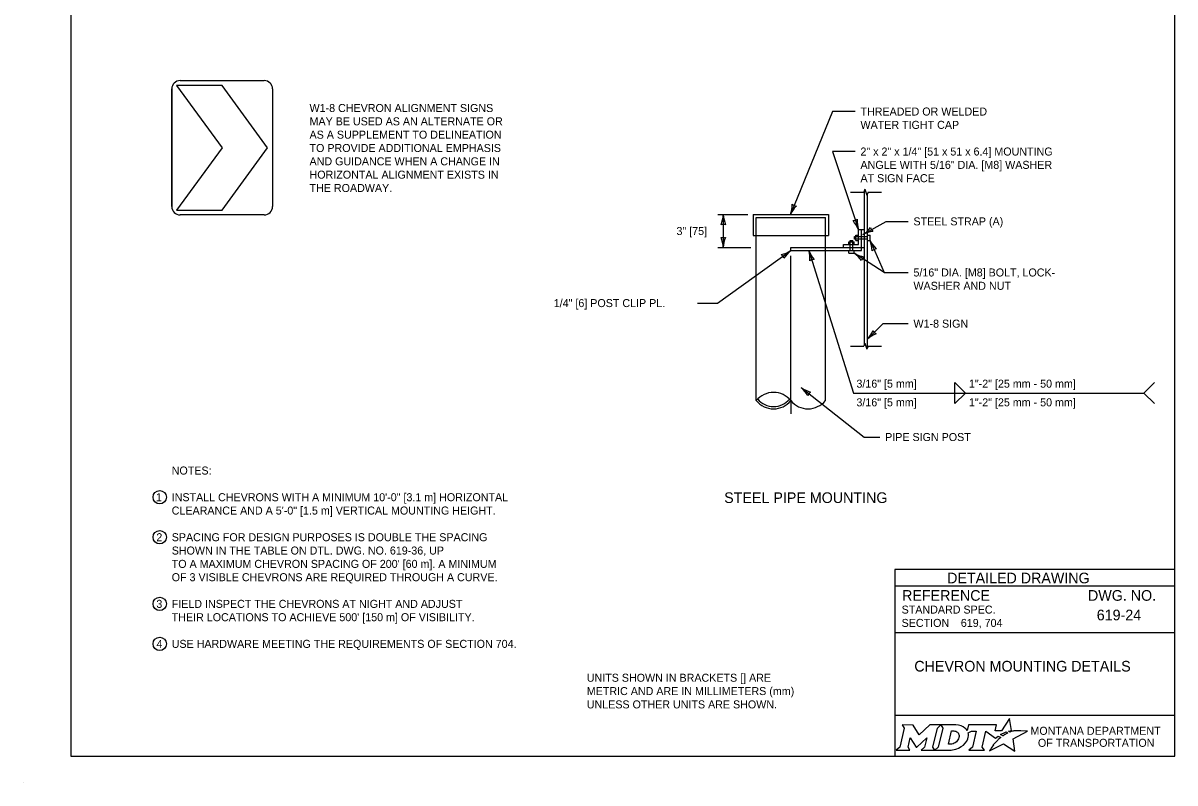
# Model space of a CAD drawing. Extents: x 49991.4 to 50021, y 49987.6 to 50011.4.
# Drawn here: x 49999.98 to 50008.61, y 49999.86 to 50005.56 of the extents above; entities that cross this region are included whole.
import ezdxf

# ---------------------------------------------------------------- set-up
doc = ezdxf.new("R2010")
doc.units = 0
for name, color, linetype in [('Level 1', 7, 'Continuous'), ('Level 2', 7, 'Continuous'), ('Level 3', 7, 'Continuous'), ('Level 4', 7, 'Continuous'), ('Level 5', 7, 'Continuous'), ('Level 6', 7, 'Continuous')]:
    doc.layers.add(name, color=color, linetype=linetype)

msp = doc.modelspace()

# ---------------------------------------------------------------- linework, layer by layer
at = {"layer": 'Level 1'}
for p, q in [((50001.1545, 50005.131), (50001.7845, 50005.131)), ((50001.0915, 50004.186), (50001.0915, 50005.068)), ((50001.0915, 50004.186), (50001.0915, 50005.068)), ((50001.0915, 50005.068), (50001.0915, 50004.186)), ((50001.4695, 50005.0943), (50001.1282, 50005.0943)), ((50001.1282, 50005.0943), (50001.4695, 50004.627)), ((50001.8107, 50004.627), (50001.4695, 50005.0943)), ((50001.8475, 50005.068), (50001.8475, 50004.186)), ((50001.4695, 50004.627), (50001.1282, 50004.1598)), ((50001.4695, 50004.1598), (50001.8107, 50004.627)), ((50006.2854, 50003.1528), (50006.2854, 50004.3074)), ((50006.3079, 50003.1248), (50006.3079, 50004.2794)), ((50001.1282, 50004.1598), (50001.4695, 50004.1598)), ((50001.7845, 50004.123), (50001.1545, 50004.123)), ((50005.4528, 50004.1261), (50006.0154, 50004.1261)), ((50005.4528, 50004.1261), (50005.4528, 50003.9686)), ((50006.0154, 50004.1261), (50006.0154, 50003.9686)), ((50006.2404, 50003.9011), (50006.2404, 50004.0136)), ((50006.2404, 50004.0136), (50006.2854, 50004.0136)), ((50006.2629, 50003.8561), (50006.2629, 50004.0136)), ((50005.4528, 50003.9686), (50006.0154, 50003.9686)), ((50005.4753, 50002.7302), (50005.4753, 50003.9686)), ((50005.9929, 50002.7308), (50005.9929, 50003.9686)), ((50006.1695, 50003.9211), (50006.2095, 50003.9211)), ((50006.1695, 50003.9011), (50006.1695, 50003.9211)), ((50006.1795, 50003.8561), (50006.1795, 50003.9311)), ((50006.1795, 50003.9311), (50006.1995, 50003.9311)), ((50006.1995, 50003.8561), (50006.1995, 50003.9311)), ((50006.2095, 50003.9011), (50006.2095, 50003.9211)), ((50006.2104, 50003.9411), (50006.2104, 50003.9611)), ((50006.2104, 50003.9611), (50006.3079, 50003.9611)), ((50006.3079, 50003.9411), (50006.2104, 50003.9411)), ((50006.2204, 50003.9311), (50006.2204, 50003.9711)), ((50006.2204, 50003.9711), (50006.2404, 50003.9711)), ((50006.2204, 50003.9311), (50006.2404, 50003.9311)), ((50006.3079, 50003.9711), (50006.3279, 50003.9711)), ((50006.3079, 50003.9311), (50006.3279, 50003.9311)), ((50006.3279, 50003.9311), (50006.3279, 50003.9711)), ((50005.7341, 50003.8786), (50006.2854, 50003.8786)), ((50005.7341, 50003.8561), (50005.7341, 50003.8786)), ((50005.7341, 50003.8561), (50006.2629, 50003.8561)), ((50006.1279, 50003.9011), (50006.2404, 50003.9011)), ((50006.1279, 50003.8786), (50006.1279, 50003.9011)), ((50006.1695, 50003.8361), (50006.1695, 50003.8561)), ((50006.1695, 50003.8361), (50006.2095, 50003.8361)), ((50006.2095, 50003.8361), (50006.2095, 50003.8561)), ((50006.2629, 50003.8561), (50006.2629, 50003.8786)), ((49999.9766, 49999.8624), (49999.9766, 49999.8624))]:
    msp.add_line(p, q, dxfattribs=at)
msp.add_lwpolyline([(50008.6146, 50011.2628), (50000.3356, 50011.2628), (50000.3356, 50000.0624), (50008.6146, 50000.0624)], close=True, dxfattribs=at)
for centre, radius, start, end in [((50001.1545, 50005.068), 0.063, 90, 180), ((50001.7845, 50005.068), 0.063, 0, 90), ((50001.1545, 50004.186), 0.063, 180, 270), ((50001.7845, 50004.186), 0.063, 270, 0), ((50005.6047, 50002.6249), 0.1668, 39.18708, 140.8762), ((50005.6047, 50002.8356), 0.1669, 219.16718, 320.85631), ((50005.6047, 50002.8388), 0.1534, 219.15498, 320.84411), ((50005.8633, 50002.8356), 0.1667, 219.17071, 321.03614)]:
    msp.add_arc(centre, radius, start, end, dxfattribs=at)
at = {"layer": 'Level 2'}
for p, q in [((50008.6146, 50001.4624), (50006.5146, 50001.4624)), ((50006.5146, 50001.4624), (50006.5146, 50000.0624)), ((50008.6146, 50001.3374), (50006.5146, 50001.3374)), ((50008.2507, 50001.1223), (50008.2507, 50001.1223)), ((50008.6146, 50000.9874), (50006.5146, 50000.9874)), ((50007.0089, 50001.0629), (50007.0089, 50001.0629)), ((50007.5646, 50000.7383), (50007.5646, 50000.7383)), ((50008.6146, 50000.3693), (50006.5146, 50000.3693))]:
    msp.add_line(p, q, dxfattribs=at)
for points in [[(50006.5701, 50000.2974), (50006.5842, 50000.274), (50006.5507, 50000.1307), (50006.525, 50000.1082), (50006.6266, 50000.1082), (50006.6131, 50000.131), (50006.6293, 50000.2011), (50006.673, 50000.1321), (50006.6783, 50000.1321), (50006.7534, 50000.2016), (50006.737, 50000.1305), (50006.7123, 50000.1085), (50006.8139, 50000.1085), (50006.8001, 50000.1318), (50006.8333, 50000.2742)], [(50006.8333, 50000.2742), (50006.8586, 50000.2974), (50006.7762, 50000.2974), (50006.6966, 50000.2244), (50006.6521, 50000.2971), (50006.5701, 50000.2974)], [(50006.9722, 50000.2974), (50006.8586, 50000.2974), (50006.8733, 50000.2745), (50006.8394, 50000.1307), (50006.8139, 50000.1085), (50006.9245, 50000.1085)], [(50007.3771, 50000.2447), (50007.3668, 50000.2503), (50007.3784, 50000.2531), (50007.39, 50000.2551), (50007.3726, 50000.3452), (50007.3131, 50000.2539), (50007.2658, 50000.2532), (50007.2761, 50000.2973), (50007.0669, 50000.2974), (50007.0568, 50000.2549), (50007.051, 50000.2632)], [(50006.9962, 50000.2107), (50006.995, 50000.2026), (50006.9918, 50000.1933), (50006.9876, 50000.1851), (50006.982, 50000.1776), (50006.9755, 50000.1707), (50006.9676, 50000.1644), (50006.9593, 50000.1597), (50006.9502, 50000.1558), (50006.9411, 50000.1535), (50006.9319, 50000.1526), (50006.916, 50000.1526), (50006.9396, 50000.2526), (50006.9556, 50000.2526), (50006.9632, 50000.252), (50006.9708, 50000.2501), (50006.9774, 50000.2471), (50006.9835, 50000.2429), (50006.9883, 50000.2379), (50006.992, 50000.2319), (50006.9947, 50000.2257), (50006.9963, 50000.2183), (50006.9963, 50000.2153), (50006.9962, 50000.2107)], [(50007.0636, 50000.2383), (50007.0882, 50000.2514), (50007.1251, 50000.2514), (50007.0965, 50000.1309), (50007.069, 50000.1082), (50007.1852, 50000.1082), (50007.1682, 50000.1311), (50007.1964, 50000.2513), (50007.2677, 50000.1996), (50007.2888, 50000.2147), (50007.3085, 50000.2038)], [(50007.2527, 50000.1479), (50007.2374, 50000.1235), (50007.2327, 50000.116), (50007.2269, 50000.1074), (50007.2246, 50000.1031), (50007.3299, 50000.1562), (50007.4138, 50000.1011), (50007.4007, 50000.1938), (50007.5076, 50000.2522), (50007.4583, 50000.253), (50007.4282, 50000.2534), (50007.4074, 50000.2537), (50007.4006, 50000.2522), (50007.3957, 50000.251), (50007.3873, 50000.2487), (50007.3771, 50000.2447)], [(50007.3267, 50000.2171), (50007.3243, 50000.2154), (50007.306, 50000.225), (50007.3163, 50000.2307), (50007.3204, 50000.2329), (50007.329, 50000.2369), (50007.3347, 50000.2395), (50007.3426, 50000.2425), (50007.3499, 50000.2452), (50007.3617, 50000.2378), (50007.3577, 50000.2357), (50007.3531, 50000.2332), (50007.3489, 50000.231), (50007.3439, 50000.2281), (50007.342, 50000.227), (50007.3393, 50000.2254), (50007.3368, 50000.224), (50007.3345, 50000.2224), (50007.3319, 50000.2206), (50007.3292, 50000.2188), (50007.3267, 50000.2171)], [(50006.9702, 50000.1158), (50006.9786, 50000.1184), (50006.9916, 50000.1238), (50007.012, 50000.1348)], [(50007.2666, 50000.164), (50007.2666, 50000.164)]]:
    msp.add_lwpolyline(points, dxfattribs=at)
for centre in [(50001.0015, 50002.0058), (50001.0015, 50001.7058), (50001.0015, 50001.2058), (50001.0015, 50000.9058)]:
    msp.add_circle(centre, 0.05, dxfattribs=at)
for centre, radius, start, end in [((50006.9953, 50000.219), 0.0709, 339.53292, 15.85821), ((50006.9513, 50000.2363), 0.1183, 300.91025, 339.13831)]:
    msp.add_arc(centre, radius, start, end, dxfattribs=at)
for centre, major_axis, ratio, start_param, end_param in [((50006.9701, 50000.25), (0.0834, -0.0037), 0.568097, 0.61298, 1.570796), ((50007.0257, 50000.2573), (0.0361, -0.0295), 0.469099, 1.225588, 1.570796), ((50007.2974, 50000.1941), (-0.0112, -0.0097), 0.021651, 3.157348, 6.283185), ((50006.9248, 50000.2568), (0, 0.1484), 0.987302, 3.139398, 3.456847), ((50007.2597, 50000.1559), (-0.00694, -0.00806), 0.008222, 0, 3.137361), ((50007.2764, 50000.1742), (-0.0098, -0.0102), 0.016458, 3.141593, 6.279097)]:
    msp.add_ellipse(centre, major_axis=major_axis, ratio=ratio, start_param=start_param, end_param=end_param, dxfattribs=at)
at = {"layer": 'Level 3'}
for p, q in [((50006.0462, 50004.8988), (50005.7313, 50004.1261)), ((50006.2162, 50004.8988), (50006.0462, 50004.8988)), ((50006.0462, 50004.5988), (50006.2404, 50004.0136)), ((50006.2162, 50004.5988), (50006.0462, 50004.5988)), ((50005.1878, 50004.1261), (50005.4128, 50004.1261)), ((50005.2278, 50004.1261), (50005.2278, 50003.8786)), ((50006.2746, 50003.9764), (50006.448, 50004.0747)), ((50006.448, 50004.0747), (50006.6137, 50004.0747)), ((50006.3279, 50003.9311), (50006.4349, 50003.6915)), ((50005.1845, 50003.4619), (50005.7341, 50003.8561)), ((50005.1878, 50003.8786), (50005.4353, 50003.8786)), ((50005.8701, 50003.8561), (50006.2045, 50002.7875)), ((50006.4349, 50003.6915), (50006.2095, 50003.8361)), ((50006.4349, 50003.6915), (50006.6137, 50003.6915)), ((50005.0332, 50003.4619), (50005.1845, 50003.4619)), ((50006.4272, 50003.3076), (50006.3079, 50003.1912)), ((50006.4272, 50003.3076), (50006.6137, 50003.3076)), ((50005.8125, 50002.8278), (50006.283, 50002.4571)), ((50006.9649, 50002.7075), (50006.9649, 50002.8675)), ((50006.2045, 50002.7875), (50008.38, 50002.7875)), ((50006.283, 50002.4571), (50006.4015, 50002.4571))]:
    msp.add_line(p, q, dxfattribs=at)
for points in [[(50006.9649, 50002.8675), (50007.0449, 50002.7875), (50006.9649, 50002.7075)], [(50008.46, 50002.7075), (50008.38, 50002.7875), (50008.46, 50002.8675)]]:
    msp.add_lwpolyline(points, dxfattribs=at)
for centre, radius, start, end in [((50005.5114, 50004.2033), 0.233, 340.65412, 359.90397), ((50005.9335, 50004.0338), 0.2223, 135.28282, 155.46633), ((50005.7797, 50004.2448), 0.0548, 229.96563, 265.68799), ((50005.0057, 50004.1353), 0.2223, 337.45601, 357.63952), ((50005.4605, 50004.1376), 0.233, 182.82731, 202.07716), ((50006.2, 50004.1353), 0.0548, 270.49737, 306.21973), ((50006.4541, 50004.0749), 0.2223, 175.81456, 195.99807), ((50005.2278, 50003.9979), 0.0548, 72.13882, 107.86118), ((50006.0232, 50003.9294), 0.233, 21.18586, 40.43571), ((50006.1498, 50004.1732), 0.233, 302.3761, 321.62595), ((50006.3861, 50004.0396), 0.0548, 191.68761, 227.40997), ((50005.2278, 50004.0068), 0.0548, 252.13882, 287.86118), ((50004.9951, 50003.8671), 0.233, 2.82731, 22.07716), ((50005.4499, 50003.8694), 0.2223, 157.45601, 177.63952), ((50006.3762, 50003.7786), 0.2223, 97.0048, 117.18831), ((50006.1213, 50003.8489), 0.2223, 1.52048, 21.70399), ((50006.5357, 50004.0365), 0.233, 206.89178, 226.14163), ((50005.6121, 50004.0419), 0.2223, 283.10595, 303.28946), ((50005.8791, 50003.6737), 0.233, 128.47725, 147.7271), ((50005.6554, 50003.7985), 0.2223, 354.83117, 15.01468), ((50006.0888, 50003.9366), 0.233, 200.20247, 219.45232), ((50006.0818, 50003.6541), 0.2223, 34.77142, 54.95493), ((50006.3255, 50004.0382), 0.233, 240.14272, 259.39257), ((50006.3802, 50003.814), 0.0548, 96.20329, 131.92565), ((50005.6299, 50003.7814), 0.0548, 17.78876, 53.51112), ((50005.9084, 50003.7337), 0.0548, 89.51398, 125.23634), ((50006.3174, 50003.7669), 0.0548, 129.45423, 165.17659), ((50006.1372, 50003.3497), 0.233, 317.12239, 336.37224), ((50006.4565, 50003.0258), 0.2223, 111.75109, 131.9346), ((50006.3997, 50003.2807), 0.0548, 206.4339, 242.15626), ((50005.6678, 50002.659), 0.2223, 29.22196, 49.40547), ((50005.9475, 50003.0177), 0.233, 234.59326, 253.84311), ((50005.9132, 50002.7485), 0.0548, 123.90477, 159.62713)]:
    msp.add_arc(centre, radius, start, end, dxfattribs=at)
at = {"layer": 'Level 4'}
for p, q in [((50005.4753, 50003.9686), (50005.4753, 50004.1036)), ((50005.4753, 50004.1036), (50005.9929, 50004.1036)), ((50005.9929, 50003.9686), (50005.9929, 50004.1036))]:
    msp.add_line(p, q, dxfattribs=at)
at = {"layer": 'Level 5'}
for q in [(50005.7341, 50003.8161), (50005.7341, 50002.6303)]:
    msp.add_line((50005.7341, 50002.7303), q, dxfattribs=at)
at = {"layer": 'Level 6'}
for p, q in [((50006.1805, 50004.2935), (50006.2805, 50004.2935)), ((50006.2886, 50004.3164), (50006.2805, 50004.2935)), ((50006.2886, 50004.3164), (50006.2967, 50004.2935)), ((50006.2967, 50004.2935), (50006.3048, 50004.2706)), ((50006.3129, 50004.2935), (50006.3048, 50004.2706)), ((50006.3129, 50004.2935), (50006.4129, 50004.2935)), ((50006.1805, 50003.1389), (50006.2805, 50003.1389)), ((50006.2886, 50003.1618), (50006.2805, 50003.1389)), ((50006.2886, 50003.1618), (50006.2967, 50003.1389)), ((50006.2967, 50003.1389), (50006.3048, 50003.116)), ((50006.3129, 50003.1389), (50006.3048, 50003.116)), ((50006.3129, 50003.1389), (50006.4129, 50003.1389))]:
    msp.add_line(p, q, dxfattribs=at)

# ---------------------------------------------------------------- texts
at = {"layer": 'Level 2'}
for s, height, p in [('W1-8 CHEVRON ALIGNMENT SIGNS', 0.06, (50002.125, 50004.8952)), ('THREADED OR WELDED', 0.06, (50006.2562, 50004.8688)), ('MAY BE USED AS AN ALTERNATE OR', 0.06, (50002.125, 50004.7952)), ('WATER TIGHT CAP', 0.06, (50006.2562, 50004.7688)), ('AS A SUPPLEMENT TO DELINEATION', 0.06, (50002.125, 50004.6952)), ('TO PROVIDE ADDITIONAL EMPHASIS', 0.06, (50002.125, 50004.5952)), ('2" x 2" x 1/4" [51 x 51 x 6.4] MOUNTING', 0.06, (50006.2562, 50004.5688)), ('AND GUIDANCE WHEN A CHANGE IN', 0.06, (50002.125, 50004.4952)), ('ANGLE WITH 5/16" DIA. [M8] WASHER', 0.06, (50006.2562, 50004.4688)), ('HORIZONTAL ALIGNMENT EXISTS IN', 0.06, (50002.125, 50004.3952)), ('THE ROADWAY.', 0.06, (50002.125, 50004.2952)), ('AT SIGN FACE', 0.06, (50006.2562, 50004.3688)), ('STEEL STRAP (A)', 0.06, (50006.6537, 50004.0447)), ('3" [75]', 0.06, (50004.8767, 50003.9724)), ('5/16" DIA. [M8] BOLT, LOCK-', 0.06, (50006.6537, 50003.6615)), ('WASHER AND NUT', 0.06, (50006.6537, 50003.5615)), ('1/4" [6] POST CLIP PL.', 0.06, (50003.9564, 50003.4319)), ('W1-8 SIGN', 0.06, (50006.6537, 50003.2776)), ('3/16" [5 mm]', 0.06, (50006.2259, 50002.8275)), ('1"-2" [25 mm - 50 mm]', 0.06, (50007.0696, 50002.8275)), ('3/16" [5 mm]', 0.06, (50006.2259, 50002.6875)), ('1"-2" [25 mm - 50 mm]', 0.06, (50007.0696, 50002.6875)), ('PIPE SIGN POST', 0.06, (50006.4415, 50002.4271)), ('NOTES:', 0.06, (50001.0915, 50002.1758)), ('1', 0.06, (50000.9733, 50001.9758)), ('INSTALL CHEVRONS WITH A MINIMUM 10\'-0" [3.1 m] HORIZONTAL', 0.06, (50001.0915, 50001.9758)), ('STEEL PIPE MOUNTING', 0.08, (50005.2344, 50001.9623)), ('CLEARANCE AND A 5\'-0" [1.5 m] VERTICAL MOUNTING HEIGHT.', 0.06, (50001.0915, 50001.8758)), ('2', 0.06, (50000.9763, 50001.6758)), ('SPACING FOR DESIGN PURPOSES IS DOUBLE THE SPACING', 0.06, (50001.0915, 50001.6758)), ('SHOWN IN THE TABLE ON DTL. DWG. NO. 619-36, UP', 0.06, (50001.0915, 50001.5758)), ("TO A MAXIMUM CHEVRON SPACING OF 200' [60 m]. A MINIMUM", 0.06, (50001.0915, 50001.4758)), ('OF 3 VISIBLE CHEVRONS ARE REQUIRED THROUGH A CURVE.', 0.06, (50001.0915, 50001.3758)), ('DETAILED DRAWING', 0.0799, (50006.9063, 50001.3599)), ('3', 0.06, (50000.9763, 50001.1758)), ('FIELD INSPECT THE CHEVRONS AT NIGHT AND ADJUST ', 0.06, (50001.0915, 50001.1758)), ('REFERENCE', 0.08, (50006.5682, 50001.229)), ('DWG. NO.', 0.08, (50007.9624, 50001.229)), ('STANDARD SPEC.', 0.06, (50006.5649, 50001.133)), ('619-24', 0.08, (50008.0281, 50001.0823)), ("THEIR LOCATIONS TO ACHIEVE 500' [150 m] OF VISIBILITY.", 0.06, (50001.0915, 50001.0758)), ('SECTION', 0.06, (50006.5649, 50001.033)), ('619, 704', 0.06, (50007.0089, 50001.0329)), ('4', 0.06, (50000.9775, 50000.8758)), ('USE HARDWARE MEETING THE REQUIREMENTS OF SECTION 704.', 0.06, (50001.0915, 50000.8758)), ('CHEVRON MOUNTING DETAILS', 0.08, (50006.66, 50000.6983)), ('UNITS SHOWN IN BRACKETS [] ARE ', 0.06, (50004.204, 50000.6217)), ('METRIC AND ARE IN MILLIMETERS (mm) ', 0.06, (50004.204, 50000.5217)), ('UNLESS OTHER UNITS ARE SHOWN.', 0.06, (50004.204, 50000.4217)), ('MONTANA DEPARTMENT', 0.06, (50007.5308, 50000.2236)), ('OF TRANSPORTATION', 0.06, (50007.587, 50000.1336))]:
    msp.add_text(s, height=height, dxfattribs=at).set_placement(p)

doc.saveas('drawing.dxf')
